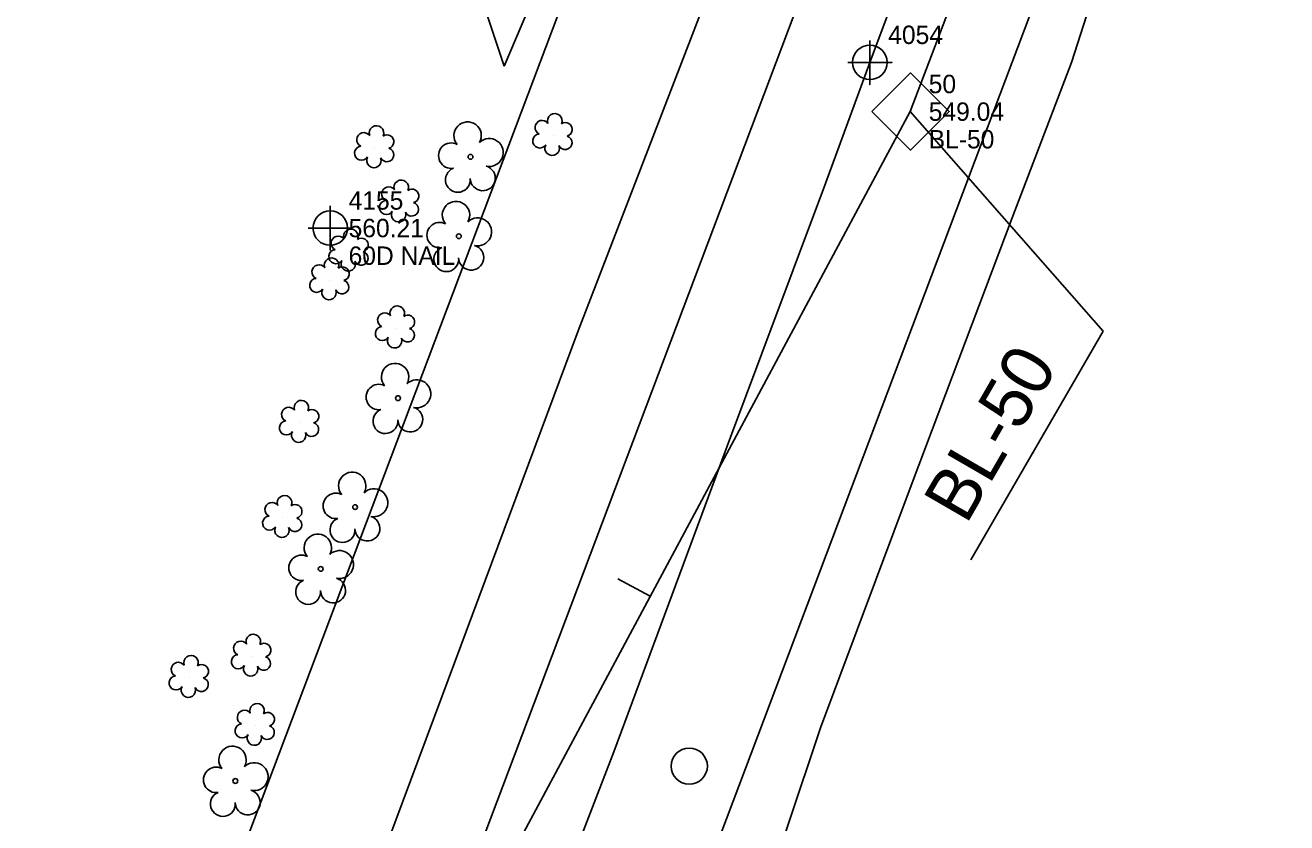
# Model space of a CAD drawing. Extents: x 1653123 to 1656194, y 596584 to 600233.
# Drawn here: x 1653449.8 to 1653621.2, y 597494.4 to 597602.7 of the extents above; entities that cross this region are included whole.
import ezdxf

# ---------------------------------------------------------------- set-up
doc = ezdxf.new("R2010")
doc.units = 0
for name, color, linetype in [('CTL Supplemental Horizontal and Vertical CELL', 7, 'Continuous'), ('CTL Supplemental Horizontal and Vertical Cogo Comment', 7, 'Continuous'), ('CTL Supplemental Horizontal and Vertical Cogo Elevation', 7, 'Continuous'), ('CTL Supplemental Horizontal and Vertical Cogo Number', 7, 'Continuous'), ('Default Symbol CELL', 7, 'Continuous'), ('Default Symbol Cogo Comment', 7, 'Continuous'), ('Default Symbol Cogo Elevation', 7, 'Continuous'), ('Default Symbol Cogo Number', 7, 'Continuous'), ('Exist Horizontal Alignment', 7, 'Continuous'), ('Exist Horizontal Baseline Alignment', 7, 'Continuous'), ('Exist Horizontal Baseline Alignment Station Label', 7, 'Continuous'), ('Exist Horizontal Baseline Alignment Tick small', 7, 'Continuous'), ('Exist Right of Way Line', 7, 'Continuous'), ('Exist Roads EOP Cogo Point CELL', 7, 'Continuous'), ('Exist Vegetation Tree CELL', 7, 'Continuous'), ('Exist Vegetation Woods Line', 7, 'Continuous'), ('Prop Conc Shoulder Berm Gutter', 7, 'Continuous'), ('Prop Horizontal Alignment', 7, 'Continuous'), ('Prop Paved Shoulder', 7, 'Continuous'), ('Prop Superelevation Label', 7, 'Continuous')]:
    doc.layers.add(name, color=color, linetype=linetype)

msp = doc.modelspace()

# ---------------------------------------------------------------- linework, layer by layer
at = {"layer": 'CTL Supplemental Horizontal and Vertical CELL'}
msp.add_line((1653570.02, 597590.97), (1653570.02, 597590.97), dxfattribs=at)
msp.add_line((1653570.02, 597590.97), (1653570.02, 597590.97), dxfattribs=at)
msp.add_lwpolyline([(1653564.8, 597590.99), (1653570.05, 597596.23), (1653575.3, 597590.98), (1653570.06, 597585.74)], close=True, dxfattribs=at)
msp.add_lwpolyline([(1653564.8, 597590.99), (1653570.05, 597596.23), (1653575.3, 597590.98), (1653570.06, 597585.74)], close=True, dxfattribs=at)
at = {"layer": 'Default Symbol CELL'}
msp.add_lwpolyline([(1653491.21, 597578.16), (1653491.21, 597572.16), (1653491.21, 597575.16), (1653494.21, 597575.16), (1653488.21, 597575.16)], dxfattribs=at)
msp.add_lwpolyline([(1653491.21, 597578.16), (1653491.21, 597572.16), (1653491.21, 597575.16), (1653494.21, 597575.16), (1653488.21, 597575.16)], dxfattribs=at)
msp.add_circle((1653491.21, 597575.16), 2.34, dxfattribs=at)
msp.add_circle((1653491.21, 597575.16), 2.34, dxfattribs=at)
at = {"layer": 'Exist Horizontal Alignment'}
msp.add_line((1653433.85, 597285.5), (1653572.84, 597653.41), dxfattribs=at)
at = {"layer": 'Exist Horizontal Baseline Alignment'}
for p, q in [((1653570.02, 597590.97), (1653732.12, 598018.79)), ((1653250.96, 596996.49), (1653570.02, 597590.97))]:
    msp.add_line(p, q, dxfattribs=at)
at = {"layer": 'Exist Horizontal Baseline Alignment Station Label'}
for p, q in [((1653570.02, 597590.97), (1653596.2, 597561.17)), ((1653596.2, 597561.17), (1653578.22, 597530.12))]:
    msp.add_line(p, q, dxfattribs=at)
at = {"layer": 'Exist Horizontal Baseline Alignment Tick small'}
msp.add_line((1653534.7, 597525.16), (1653530.29, 597527.53), dxfattribs=at)
at = {"layer": 'Exist Right of Way Line'}
for p, q in [((1653405.78, 597296.1), (1653544.78, 597664.01)), ((1653461.91, 597274.9), (1653600.91, 597642.81))]:
    msp.add_line(p, q, dxfattribs=at)
at = {"layer": 'Exist Roads EOP Cogo Point CELL'}
msp.add_lwpolyline([(1653564.52, 597600.65), (1653564.52, 597594.65), (1653564.52, 597597.65), (1653567.52, 597597.65), (1653561.52, 597597.65)], dxfattribs=at)
msp.add_circle((1653564.52, 597597.65), 2.34, dxfattribs=at)
at = {"layer": 'Exist Vegetation Tree CELL'}
for p, q in [((1653510.27, 597584.83), (1653510.27, 597584.83)), ((1653508.68, 597574.05), (1653508.68, 597574.05)), ((1653500.42, 597552.06), (1653500.42, 597552.06)), ((1653494.59, 597537.27), (1653494.59, 597537.27)), ((1653489.92, 597528.87), (1653489.92, 597528.87)), ((1653478.32, 597500.07), (1653478.32, 597500.07))]:
    msp.add_line(p, q, dxfattribs=at)
for centre in [(1653510.27, 597584.83), (1653508.68, 597574.05), (1653500.42, 597552.06), (1653494.59, 597537.27), (1653489.92, 597528.87), (1653478.32, 597500.07)]:
    msp.add_circle(centre, 0.326, dxfattribs=at)
for centre, radius, start, end in [((1653509.88, 597587.71), 1.86, 330.1651, 219.7134), ((1653512.82, 597585.42), 1.9, 257.1011, 134.1999), ((1653507.66, 597584.99), 1.73, 62.6636, 279.3457), ((1653508.56, 597581.71), 1.69, 111.5671, 6.231), ((1653511.94, 597581.93), 1.7, 181.2822, 74.56), ((1653508.3, 597576.92), 1.86, 330.1651, 219.7134), ((1653506.08, 597574.2), 1.73, 62.6636, 279.3457), ((1653511.23, 597574.64), 1.9, 257.1011, 134.1999), ((1653506.98, 597570.93), 1.69, 111.5671, 6.231), ((1653510.36, 597571.15), 1.7, 181.2822, 74.56), ((1653500.03, 597554.93), 1.86, 330.1651, 219.7134), ((1653497.81, 597552.21), 1.73, 62.6636, 279.3457), ((1653502.97, 597552.65), 1.9, 257.1011, 134.1999), ((1653498.71, 597548.94), 1.69, 111.5671, 6.231), ((1653502.09, 597549.16), 1.7, 181.2822, 74.56), ((1653494.2, 597540.15), 1.86, 330.1651, 219.7134), ((1653497.14, 597537.86), 1.9, 257.1011, 134.1999), ((1653491.98, 597537.43), 1.73, 62.6636, 279.3457), ((1653496.26, 597534.37), 1.7, 181.2822, 74.56), ((1653492.88, 597534.15), 1.69, 111.5671, 6.231), ((1653489.53, 597531.74), 1.86, 330.1651, 219.7134), ((1653492.47, 597529.46), 1.9, 257.1011, 134.1999), ((1653487.31, 597529.02), 1.73, 62.6636, 279.3457), ((1653491.59, 597525.97), 1.7, 181.2822, 74.56), ((1653488.21, 597525.75), 1.69, 111.5671, 6.231), ((1653477.94, 597502.94), 1.86, 330.1651, 219.7134), ((1653475.72, 597500.22), 1.73, 62.6636, 279.3457), ((1653480.87, 597500.66), 1.9, 257.1011, 134.1999), ((1653476.62, 597496.95), 1.69, 111.5671, 6.231), ((1653480, 597497.17), 1.7, 181.2822, 74.56)]:
    msp.add_arc(centre, radius, start, end, dxfattribs=at)
at = {"layer": 'Exist Vegetation Woods Line'}
for points in [[(1653514.84, 597597.16), (1653477.21, 597709.86), (1653491.17, 597745.19), (1653533.5, 597737.69), (1653554.74, 597690.96), (1653514.84, 597597.16)], [(1653524.57, 597398.54), (1653534.97, 597420.27), (1653541.96, 597436.88), (1653544.17, 597450.83), (1653545.7, 597465.03), (1653548.89, 597480.65), (1653557.83, 597507.27), (1653570.27, 597540.55), (1653583.86, 597576.56), (1653591.94, 597597.65), (1653607.08, 597644.86), (1653612.18, 597657.29), (1653623.35, 597688.62)]]:
    msp.add_lwpolyline(points, dxfattribs=at)
at = {"layer": 'Prop Conc Shoulder Berm Gutter'}
for points in [[(1653564.52, 597597.65), (1653581.19, 597642.12), (1653595.32, 597679.04), (1653605.24, 597704.17), (1653614.92, 597727.36), (1653625.98, 597753.19), (1653641.03, 597786.45), (1653655.92, 597818.68), (1653671.74, 597850.93), (1653688.35, 597883.45), (1653707.13, 597918.97), (1653720.66, 597943.73), (1653734.86, 597970.07), (1653749.84, 597996.36), (1653750.81, 597997.29)], [(1653472.35, 597421.43), (1653481.44, 597445.07), (1653491.47, 597471.59), (1653506.36, 597511.5), (1653524.9, 597561.22), (1653542.08, 597605.71)], [(1653564.52, 597597.65), (1653558.38, 597580.84), (1653545.57, 597546.76), (1653529.73, 597504.01), (1653515.62, 597467.42), (1653493.76, 597408.77)]]:
    msp.add_lwpolyline(points, dxfattribs=at)
at = {"layer": 'Prop Paved Shoulder'}
msp.add_circle((1653539.99, 597502.09), 2.46, dxfattribs=at)
at = {"layer": 'Prop Superelevation Label'}
for p, q in [((1653521.49, 597587.68), (1653521.49, 597587.68)), ((1653497.27, 597586.02), (1653497.27, 597586.02)), ((1653500.64, 597578.65), (1653500.64, 597578.65)), ((1653493.78, 597571.98), (1653493.78, 597571.98)), ((1653491.17, 597568.08), (1653491.17, 597568.08)), ((1653500.09, 597561.55), (1653500.09, 597561.55)), ((1653487.06, 597548.73), (1653487.06, 597548.73)), ((1653484.78, 597535.81), (1653484.78, 597535.81)), ((1653480.53, 597516.97), (1653480.53, 597516.97)), ((1653472.07, 597514.09), (1653472.07, 597514.09)), ((1653481.04, 597507.58), (1653481.04, 597507.58))]:
    msp.add_line(p, q, dxfattribs=at)
for centre, radius, start, end in [((1653497.5, 597588.07), 0.99, 334.8391, 200.4717), ((1653520.01, 597588.81), 0.968, 35.8908, 245.4216), ((1653521.72, 597589.72), 0.99, 334.8391, 200.4717), ((1653523.16, 597588.55), 0.929, 284.4567, 126.0861), ((1653495.79, 597587.15), 0.968, 35.8908, 245.4216), ((1653498.94, 597586.89), 0.929, 284.4567, 126.0861), ((1653519.69, 597586.98), 0.955, 95.1099, 327.9534), ((1653523.13, 597586.75), 0.937, 204.9913, 73.4601), ((1653495.47, 597585.32), 0.955, 95.1099, 327.9534), ((1653498.91, 597585.1), 0.937, 204.9913, 73.4601), ((1653521.36, 597586), 0.984, 151.2797, 21.387), ((1653497.14, 597584.34), 0.984, 151.2797, 21.387), ((1653499.15, 597579.78), 0.968, 35.8908, 245.4216), ((1653500.86, 597580.69), 0.99, 334.8391, 200.4717), ((1653498.84, 597577.95), 0.955, 95.1099, 327.9534), ((1653502.31, 597579.52), 0.929, 284.4567, 126.0861), ((1653500.51, 597576.97), 0.984, 151.2797, 21.387), ((1653502.27, 597577.72), 0.937, 204.9913, 73.4601), ((1653492.3, 597573.1), 0.968, 35.8908, 245.4216), ((1653494.01, 597574.02), 0.99, 334.8391, 200.4717), ((1653495.46, 597572.85), 0.929, 284.4567, 126.0861), ((1653491.98, 597571.27), 0.955, 95.1099, 327.9534), ((1653495.42, 597571.05), 0.937, 204.9913, 73.4601), ((1653491.4, 597570.12), 0.99, 334.8391, 200.4717), ((1653493.66, 597570.29), 0.984, 151.2797, 21.387), ((1653489.69, 597569.21), 0.968, 35.8908, 245.4216), ((1653492.85, 597568.95), 0.929, 284.4567, 126.0861), ((1653489.37, 597567.38), 0.955, 95.1099, 327.9534), ((1653491.05, 597566.4), 0.984, 151.2797, 21.387), ((1653492.81, 597567.15), 0.937, 204.9913, 73.4601), ((1653498.6, 597562.67), 0.968, 35.8908, 245.4216), ((1653500.32, 597563.59), 0.99, 334.8391, 200.4717), ((1653501.76, 597562.41), 0.929, 284.4567, 126.0861), ((1653498.29, 597560.84), 0.955, 95.1099, 327.9534), ((1653499.96, 597559.86), 0.984, 151.2797, 21.387), ((1653501.72, 597560.62), 0.937, 204.9913, 73.4601), ((1653487.29, 597550.77), 0.99, 334.8391, 200.4717), ((1653485.58, 597549.85), 0.968, 35.8908, 245.4216), ((1653488.73, 597549.59), 0.929, 284.4567, 126.0861), ((1653485.26, 597548.02), 0.955, 95.1099, 327.9534), ((1653488.7, 597547.8), 0.937, 204.9913, 73.4601), ((1653486.93, 597547.04), 0.984, 151.2797, 21.387), ((1653483.3, 597536.93), 0.968, 35.8908, 245.4216), ((1653485.01, 597537.85), 0.99, 334.8391, 200.4717), ((1653482.98, 597535.1), 0.955, 95.1099, 327.9534), ((1653486.45, 597536.68), 0.929, 284.4567, 126.0861), ((1653484.65, 597534.12), 0.984, 151.2797, 21.387), ((1653486.42, 597534.88), 0.937, 204.9913, 73.4601), ((1653479.05, 597518.1), 0.968, 35.8908, 245.4216), ((1653480.76, 597519.01), 0.99, 334.8391, 200.4717), ((1653482.21, 597517.84), 0.929, 284.4567, 126.0861), ((1653472.3, 597516.13), 0.99, 334.8391, 200.4717), ((1653478.73, 597516.27), 0.955, 95.1099, 327.9534), ((1653470.59, 597515.22), 0.968, 35.8908, 245.4216), ((1653473.74, 597514.96), 0.929, 284.4567, 126.0861), ((1653480.41, 597515.29), 0.984, 151.2797, 21.387), ((1653482.17, 597516.04), 0.937, 204.9913, 73.4601), ((1653470.27, 597513.39), 0.955, 95.1099, 327.9534), ((1653473.71, 597513.16), 0.937, 204.9913, 73.4601), ((1653471.94, 597512.41), 0.984, 151.2797, 21.387), ((1653481.27, 597509.62), 0.99, 334.8391, 200.4717), ((1653479.56, 597508.71), 0.968, 35.8908, 245.4216), ((1653482.71, 597508.45), 0.929, 284.4567, 126.0861), ((1653479.24, 597506.88), 0.955, 95.1099, 327.9534), ((1653482.68, 597506.65), 0.937, 204.9913, 73.4601), ((1653480.91, 597505.9), 0.984, 151.2797, 21.387)]:
    msp.add_arc(centre, radius, start, end, dxfattribs=at)

# ---------------------------------------------------------------- texts
at = {"layer": 'CTL Supplemental Horizontal and Vertical Cogo Comment'}
msp.add_text('BL-50', height=2.5, dxfattribs=at).set_placement((1653572.52, 597585.97))
at = {"layer": 'CTL Supplemental Horizontal and Vertical Cogo Elevation'}
msp.add_text('549.04', height=2.5, dxfattribs=at).set_placement((1653572.52, 597589.72))
at = {"layer": 'CTL Supplemental Horizontal and Vertical Cogo Number'}
msp.add_text('50', height=2.5, dxfattribs=at).set_placement((1653572.52, 597593.47))
msp.add_text('50', height=2.5, dxfattribs=at).set_placement((1653572.52, 597593.47))
at = {"layer": 'Default Symbol Cogo Comment'}
msp.add_text('60D NAIL', height=2.5, dxfattribs=at).set_placement((1653493.71, 597570.16))
at = {"layer": 'Default Symbol Cogo Elevation'}
msp.add_text('560.21', height=2.5, dxfattribs=at).set_placement((1653493.71, 597573.91))
at = {"layer": 'Default Symbol Cogo Number'}
msp.add_text('4155', height=2.5, dxfattribs=at).set_placement((1653493.71, 597577.66))
msp.add_text('4155', height=2.5, dxfattribs=at).set_placement((1653493.71, 597577.66))
at = {"layer": 'Exist Horizontal Baseline Alignment Station Label'}
msp.add_text('BL-50', height=7, rotation=59.9255, dxfattribs=at).set_placement((1653577.62, 597534.78))
at = {"layer": 'Prop Horizontal Alignment'}
msp.add_text('4054', height=2.5, dxfattribs=at).set_placement((1653567.02, 597600.15))

doc.saveas('drawing.dxf')
